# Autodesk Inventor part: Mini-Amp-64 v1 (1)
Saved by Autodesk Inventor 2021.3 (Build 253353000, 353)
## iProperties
Created: 2022-07
Part Number: Mini-Amp-64 v1 (1)
Material: Generic
Document SubType Name: Modeling
Designer: Administrator
Density: 1 g/cm^3
Appearance: Default
Title: Mini-Amp-64 v1 (1)
Author: Administrator
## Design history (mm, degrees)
